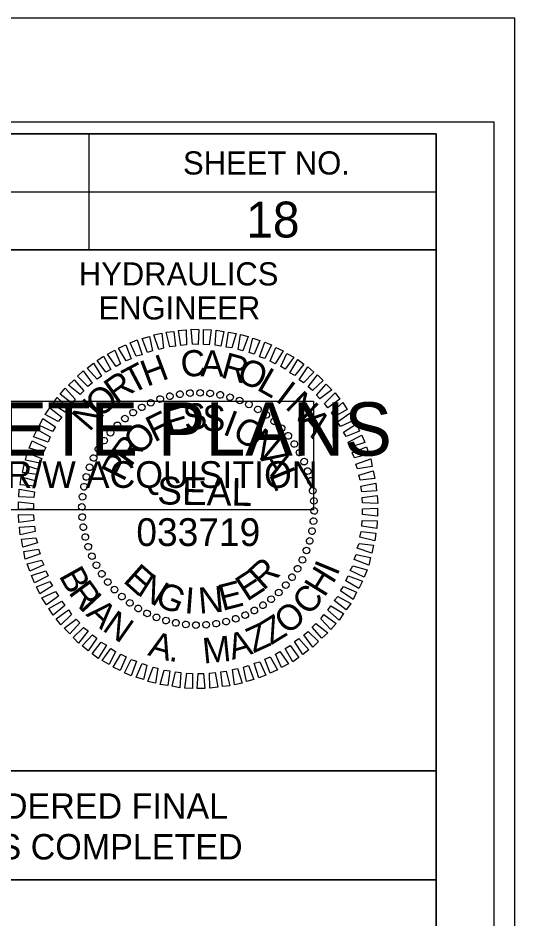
# Model space of a CAD drawing. Extents: x 1779926 to 1781610, y 605564 to 621564.
# Drawn here: x 1781502.6 to 1781610, y 606469.7 to 606664.2 of the extents above; entities that cross this region are included whole.
import ezdxf

# ---------------------------------------------------------------- set-up
doc = ezdxf.new("R2010")
doc.units = 0
for name, color, linetype in [('Old_Level_58', 7, 'Continuous'), ('Sheet Data Field CELL', 7, 'Continuous'), ('Sheet Plot Border Inside CELL', 7, 'Continuous'), ('Sheet Plot Border Outside CELL', 7, 'Continuous'), ('Sheet Professional Seal CELL', 7, 'Continuous'), ('Sheet Profile CELL', 7, 'Continuous'), ('Sheet Profile Grid Major CELL', 7, 'Continuous'), ('Sheet Profile Grid Minor CELL', 7, 'Continuous'), ('Sheet Sticker Exception Certification CELL', 7, 'Continuous'), ('Sheet Sticker Incomplete CELL', 7, 'Continuous')]:
    doc.layers.add(name, color=color, linetype=linetype)

msp = doc.modelspace()

# ---------------------------------------------------------------- linework, layer by layer
at = {"layer": 'Old_Level_58'}
msp.add_lwpolyline([(1781392.96, 606478.15), (1781592.95, 606478.15), (1781592.95, 606414.2), (1781392.96, 606414.2)], close=True, dxfattribs=at)
at = {"layer": 'Sheet Plot Border Inside CELL'}
msp.add_lwpolyline([(1779938.96, 605586.65), (1781605.46, 605586.65), (1781605.46, 606641.75), (1779938.96, 606641.75)], close=True, dxfattribs=at)
at = {"layer": 'Sheet Plot Border Outside CELL'}
msp.add_lwpolyline([(1779925.96, 605564.2), (1781609.96, 605564.2), (1781609.96, 606664.2), (1779925.96, 606664.2)], close=True, dxfattribs=at)
at = {"layer": 'Sheet Professional Seal CELL'}
for p, q in [((1781539.76, 606583.25), (1781539.76, 606583.25)), ((1781541.96, 606583.3), (1781541.96, 606583.3)), ((1781533.31, 606581.95), (1781533.31, 606581.95)), ((1781535.41, 606582.55), (1781535.41, 606582.55)), ((1781537.61, 606582.95), (1781537.61, 606582.95)), ((1781544.16, 606583.15), (1781544.16, 606583.15)), ((1781546.31, 606582.8), (1781546.31, 606582.8)), ((1781548.41, 606582.35), (1781548.41, 606582.35)), ((1781550.51, 606581.65), (1781550.51, 606581.65)), ((1781529.36, 606580.15), (1781529.36, 606580.15)), ((1781531.31, 606581.15), (1781531.31, 606581.15)), ((1781552.51, 606580.75), (1781552.51, 606580.75)), ((1781554.46, 606579.75), (1781554.46, 606579.75)), ((1781525.71, 606577.75), (1781525.71, 606577.75)), ((1781527.46, 606579), (1781527.46, 606579)), ((1781556.26, 606578.5), (1781556.26, 606578.5)), ((1781524.06, 606576.25), (1781524.06, 606576.25)), ((1781558.01, 606577.15), (1781558.01, 606577.15)), ((1781559.56, 606575.65), (1781559.56, 606575.65)), ((1781522.56, 606574.7), (1781522.56, 606574.7)), ((1781561.06, 606574), (1781561.06, 606574)), ((1781521.21, 606572.95), (1781521.21, 606572.95)), ((1781562.31, 606572.25), (1781562.31, 606572.25)), ((1781519.96, 606571.15), (1781519.96, 606571.15)), ((1781563.46, 606570.35), (1781563.46, 606570.35)), ((1781518.96, 606569.2), (1781518.96, 606569.2)), ((1781564.46, 606568.4), (1781564.46, 606568.4)), ((1781518.06, 606567.2), (1781518.06, 606567.2)), ((1781565.26, 606566.4), (1781565.26, 606566.4)), ((1781517.36, 606565.1), (1781517.36, 606565.1)), ((1781565.86, 606564.3), (1781565.86, 606564.3)), ((1781516.91, 606563), (1781516.91, 606563)), ((1781566.26, 606562.1), (1781566.26, 606562.1)), ((1781516.56, 606560.85), (1781516.56, 606560.85)), ((1781566.56, 606559.95), (1781566.56, 606559.95)), ((1781516.41, 606558.65), (1781516.41, 606558.65)), ((1781541.51, 606558.2), (1781541.51, 606558.2)), ((1781516.46, 606556.45), (1781516.46, 606556.45)), ((1781566.61, 606557.75), (1781566.61, 606557.75)), ((1781516.76, 606554.3), (1781516.76, 606554.3)), ((1781566.46, 606555.55), (1781566.46, 606555.55)), ((1781517.16, 606552.1), (1781517.16, 606552.1)), ((1781566.11, 606553.4), (1781566.11, 606553.4)), ((1781565.66, 606551.3), (1781565.66, 606551.3)), ((1781517.76, 606550), (1781517.76, 606550)), ((1781564.96, 606549.2), (1781564.96, 606549.2)), ((1781518.56, 606548), (1781518.56, 606548)), ((1781564.06, 606547.2), (1781564.06, 606547.2)), ((1781519.56, 606546.05), (1781519.56, 606546.05)), ((1781563.06, 606545.25), (1781563.06, 606545.25)), ((1781520.71, 606544.15), (1781520.71, 606544.15)), ((1781521.96, 606542.4), (1781521.96, 606542.4)), ((1781561.81, 606543.45), (1781561.81, 606543.45)), ((1781523.46, 606540.75), (1781523.46, 606540.75)), ((1781560.46, 606541.7), (1781560.46, 606541.7)), ((1781525.01, 606539.25), (1781525.01, 606539.25)), ((1781557.31, 606538.65), (1781557.31, 606538.65)), ((1781558.96, 606540.15), (1781558.96, 606540.15)), ((1781526.76, 606537.9), (1781526.76, 606537.9)), ((1781528.56, 606536.65), (1781528.56, 606536.65)), ((1781555.56, 606537.4), (1781555.56, 606537.4)), ((1781530.51, 606535.65), (1781530.51, 606535.65)), ((1781532.51, 606534.75), (1781532.51, 606534.75)), ((1781551.71, 606535.25), (1781551.71, 606535.25)), ((1781553.66, 606536.25), (1781553.66, 606536.25)), ((1781534.61, 606534.05), (1781534.61, 606534.05)), ((1781536.71, 606533.6), (1781536.71, 606533.6)), ((1781538.86, 606533.25), (1781538.86, 606533.25)), ((1781541.06, 606533.1), (1781541.06, 606533.1)), ((1781543.26, 606533.15), (1781543.26, 606533.15)), ((1781545.41, 606533.45), (1781545.41, 606533.45)), ((1781547.61, 606533.85), (1781547.61, 606533.85)), ((1781549.71, 606534.45), (1781549.71, 606534.45))]:
    msp.add_line(p, q, dxfattribs=at)
for points in [[(1781537.81, 606593.5), (1781537.26, 606596.7), (1781538.96, 606596.9), (1781539.01, 606593.65)], [(1781540.31, 606593.75), (1781540.06, 606597), (1781541.71, 606596.95), (1781541.51, 606593.7)], [(1781542.71, 606593.7), (1781542.71, 606596.95), (1781544.36, 606596.9), (1781543.91, 606593.65)], [(1781530.61, 606592), (1781529.46, 606595), (1781531.01, 606595.45), (1781531.66, 606592.35)], [(1781533.01, 606592.65), (1781531.96, 606595.8), (1781533.66, 606596.15), (1781534.06, 606592.9)], [(1781535.41, 606593.2), (1781534.61, 606596.4), (1781536.26, 606596.55), (1781536.61, 606593.35)], [(1781545.21, 606593.55), (1781545.41, 606596.8), (1781547.06, 606596.5), (1781546.41, 606593.35)], [(1781547.61, 606593.15), (1781548.06, 606596.35), (1781549.71, 606596.1), (1781548.81, 606593)], [(1781550.16, 606592.6), (1781550.66, 606595.85), (1781552.36, 606595.45), (1781551.21, 606592.35)], [(1781552.56, 606591.95), (1781553.31, 606595.05), (1781554.86, 606594.55), (1781553.61, 606591.6)], [(1781525.96, 606590.15), (1781524.36, 606592.95), (1781525.91, 606593.65), (1781527.06, 606590.6)], [(1781528.16, 606591.2), (1781526.86, 606594.1), (1781528.36, 606594.7), (1781529.41, 606591.5)], [(1781554.81, 606591.05), (1781555.96, 606594.2), (1781557.36, 606593.6), (1781555.96, 606590.7)], [(1781557.06, 606590.1), (1781558.31, 606593.05), (1781559.86, 606592.35), (1781558.16, 606589.55)], [(1781521.61, 606587.7), (1781519.76, 606590.25), (1781521.06, 606591.2), (1781522.71, 606588.3)], [(1781523.81, 606588.95), (1781521.96, 606591.65), (1781523.51, 606592.45), (1781524.76, 606589.55)], [(1781559.36, 606588.95), (1781560.71, 606591.8), (1781562.21, 606590.95), (1781560.31, 606588.35)], [(1781519.71, 606586.2), (1781517.56, 606588.6), (1781518.91, 606589.65), (1781520.66, 606586.85)], [(1781561.31, 606587.6), (1781563.06, 606590.5), (1781564.36, 606589.45), (1781562.41, 606587)], [(1781517.71, 606584.65), (1781515.51, 606586.85), (1781516.71, 606588.05), (1781518.66, 606585.35)], [(1781563.36, 606586.1), (1781565.21, 606588.85), (1781566.51, 606587.75), (1781564.31, 606585.4)], [(1781565.26, 606584.55), (1781567.31, 606587.15), (1781568.51, 606585.95), (1781566.21, 606583.8)], [(1781516.06, 606582.9), (1781513.51, 606584.95), (1781514.76, 606586.1), (1781516.86, 606583.7)], [(1781514.31, 606581), (1781511.71, 606582.95), (1781512.81, 606584.25), (1781515.01, 606581.9)], [(1781567.06, 606582.8), (1781569.21, 606585.15), (1781570.41, 606583.95), (1781567.81, 606582)], [(1781568.81, 606581), (1781571.11, 606583.25), (1781572.16, 606581.9), (1781569.51, 606580)], [(1781512.81, 606579.1), (1781510.11, 606580.8), (1781511.06, 606582.25), (1781513.46, 606580.05)], [(1781511.31, 606577.1), (1781508.51, 606578.6), (1781509.51, 606580), (1781512.11, 606578)], [(1781570.31, 606579.05), (1781572.76, 606581.15), (1781573.71, 606579.7), (1781570.91, 606578.1)], [(1781510.11, 606574.95), (1781507.26, 606576.2), (1781508.01, 606577.75), (1781510.71, 606575.9)], [(1781571.61, 606577), (1781574.26, 606578.9), (1781575.21, 606577.4), (1781572.31, 606576)], [(1781572.91, 606574.8), (1781575.71, 606576.55), (1781576.36, 606575), (1781573.51, 606573.85)], [(1781509.11, 606572.65), (1781506.01, 606573.8), (1781506.76, 606575.35), (1781509.61, 606573.75)], [(1781573.91, 606572.65), (1781576.86, 606574.15), (1781577.51, 606572.55), (1781574.41, 606571.55)], [(1781508.11, 606570.45), (1781505.01, 606571.35), (1781505.66, 606572.9), (1781508.66, 606571.5)], [(1781574.81, 606570.3), (1781577.86, 606571.6), (1781578.41, 606570.05), (1781575.31, 606569.25)], [(1781507.36, 606568.05), (1781504.26, 606568.7), (1781504.61, 606570.35), (1781507.76, 606569.1)], [(1781506.71, 606565.65), (1781503.61, 606566.05), (1781503.96, 606567.75), (1781507.11, 606566.7)], [(1781575.61, 606567.9), (1781578.81, 606569.05), (1781579.11, 606567.4), (1781575.96, 606566.85)], [(1781576.21, 606565.5), (1781579.36, 606566.45), (1781579.66, 606564.75), (1781576.51, 606564.45)], [(1781506.31, 606563.1), (1781503.11, 606563.4), (1781503.31, 606565.1), (1781506.56, 606564.3)], [(1781576.66, 606563.1), (1781579.91, 606563.8), (1781580.06, 606562.1), (1781576.86, 606561.9)], [(1781506.06, 606560.7), (1781502.81, 606560.8), (1781502.91, 606562.45), (1781506.16, 606561.9)], [(1781576.96, 606560.7), (1781580.21, 606561.1), (1781580.31, 606559.4), (1781577.06, 606559.5)], [(1781506.01, 606558.2), (1781502.76, 606558.05), (1781502.76, 606559.75), (1781506.01, 606559.4)], [(1781577.01, 606558.2), (1781580.26, 606558.35), (1781580.26, 606556.65), (1781577.01, 606557)], [(1781506.06, 606555.7), (1781502.81, 606555.3), (1781502.71, 606557), (1781505.96, 606556.9)], [(1781506.36, 606553.3), (1781503.11, 606552.6), (1781502.96, 606554.3), (1781506.16, 606554.5)], [(1781576.96, 606555.7), (1781580.21, 606555.6), (1781580.11, 606553.95), (1781576.86, 606554.5)], [(1781576.71, 606553.3), (1781579.91, 606553), (1781579.71, 606551.3), (1781576.46, 606552.1)], [(1781506.81, 606550.9), (1781503.66, 606549.95), (1781503.36, 606551.65), (1781506.51, 606551.95)], [(1781576.31, 606550.75), (1781579.41, 606550.35), (1781579.06, 606548.65), (1781575.91, 606549.7)], [(1781507.41, 606548.5), (1781504.21, 606547.35), (1781503.91, 606549), (1781507.06, 606549.55)], [(1781575.66, 606548.35), (1781578.76, 606547.7), (1781578.41, 606546.05), (1781575.26, 606547.3)], [(1781508.21, 606546.1), (1781505.16, 606544.8), (1781504.61, 606546.35), (1781507.71, 606547.15)], [(1781509.11, 606543.75), (1781506.16, 606542.25), (1781505.51, 606543.85), (1781508.61, 606544.85)], [(1781574.91, 606545.95), (1781578.01, 606545.05), (1781577.36, 606543.5), (1781574.36, 606544.9)], [(1781510.11, 606541.6), (1781507.31, 606539.85), (1781506.66, 606541.4), (1781509.51, 606542.55)], [(1781573.91, 606543.75), (1781577.01, 606542.6), (1781576.26, 606541.05), (1781573.41, 606542.65)], [(1781572.91, 606541.45), (1781575.76, 606540.2), (1781575.01, 606538.65), (1781572.31, 606540.5)], [(1781511.41, 606539.4), (1781508.76, 606537.5), (1781507.81, 606539), (1781510.71, 606540.4)], [(1781571.71, 606539.3), (1781574.51, 606537.8), (1781573.51, 606536.4), (1781570.91, 606538.4)], [(1781512.71, 606537.35), (1781510.26, 606535.25), (1781509.31, 606536.7), (1781512.11, 606538.3)], [(1781570.21, 606537.3), (1781572.91, 606535.6), (1781571.96, 606534.15), (1781569.56, 606536.35)], [(1781514.21, 606535.4), (1781511.91, 606533.15), (1781510.86, 606534.5), (1781513.51, 606536.4)], [(1781568.71, 606535.4), (1781571.31, 606533.45), (1781570.21, 606532.15), (1781568.01, 606534.5)], [(1781515.96, 606533.6), (1781513.81, 606531.25), (1781512.61, 606532.45), (1781515.21, 606534.4)], [(1781566.96, 606533.5), (1781569.51, 606531.45), (1781568.26, 606530.3), (1781566.16, 606532.7)], [(1781517.76, 606531.85), (1781515.71, 606529.25), (1781514.51, 606530.45), (1781516.81, 606532.6)], [(1781519.66, 606530.3), (1781517.81, 606527.55), (1781516.51, 606528.65), (1781518.71, 606531)], [(1781565.31, 606531.75), (1781567.51, 606529.55), (1781566.31, 606528.35), (1781564.36, 606531.05)], [(1781521.71, 606528.8), (1781519.96, 606525.9), (1781518.66, 606526.95), (1781520.61, 606529.4)], [(1781563.31, 606530.2), (1781565.46, 606527.8), (1781564.11, 606526.75), (1781562.36, 606529.55)], [(1781523.66, 606527.45), (1781522.31, 606524.6), (1781520.81, 606525.45), (1781522.71, 606528.05)], [(1781525.96, 606526.3), (1781524.71, 606523.35), (1781523.16, 606524.05), (1781524.86, 606526.85)], [(1781559.21, 606527.45), (1781561.06, 606524.75), (1781559.51, 606523.95), (1781558.26, 606526.85)], [(1781561.41, 606528.7), (1781563.26, 606526.15), (1781561.96, 606525.2), (1781560.31, 606528.1)], [(1781528.21, 606525.35), (1781527.06, 606522.2), (1781525.66, 606522.8), (1781527.06, 606525.7)], [(1781554.86, 606525.2), (1781556.16, 606522.3), (1781554.66, 606521.7), (1781553.61, 606524.9)], [(1781557.06, 606526.25), (1781558.66, 606523.45), (1781557.11, 606522.75), (1781555.96, 606525.8)], [(1781530.46, 606524.45), (1781529.71, 606521.35), (1781528.16, 606521.85), (1781529.41, 606524.8)], [(1781532.86, 606523.8), (1781532.36, 606520.55), (1781530.66, 606520.95), (1781531.81, 606524.05)], [(1781535.41, 606523.25), (1781534.96, 606520.05), (1781533.31, 606520.3), (1781534.21, 606523.4)], [(1781537.81, 606522.85), (1781537.61, 606519.6), (1781535.96, 606519.9), (1781536.61, 606523.05)], [(1781547.61, 606523.2), (1781548.41, 606520), (1781546.76, 606519.85), (1781546.41, 606523.05)], [(1781550.01, 606523.75), (1781551.06, 606520.6), (1781549.36, 606520.25), (1781548.96, 606523.5)], [(1781552.41, 606524.4), (1781553.56, 606521.4), (1781552.01, 606520.95), (1781551.36, 606524.05)], [(1781540.31, 606522.7), (1781540.31, 606519.45), (1781538.66, 606519.5), (1781539.11, 606522.75)], [(1781542.71, 606522.65), (1781542.96, 606519.4), (1781541.31, 606519.45), (1781541.51, 606522.7)], [(1781545.21, 606522.9), (1781545.76, 606519.7), (1781544.06, 606519.5), (1781544.01, 606522.75)]]:
    msp.add_lwpolyline(points, close=True, dxfattribs=at)
for centre, major_axis in [((1781535.44, 606582.54), (-0.174, 0.699)), ((1781537.59, 606582.98), (-0.113, 0.711)), ((1781539.76, 606583.22), (-0.05, 0.718)), ((1781541.95, 606583.28), (0.013, 0.72)), ((1781544.13, 606583.15), (0.075, 0.716)), ((1781546.3, 606582.82), (0.137, 0.707)), ((1781531.31, 606581.12), (-0.293, 0.658)), ((1781533.34, 606581.92), (-0.234, 0.681)), ((1781548.42, 606582.31), (0.198, 0.692)), ((1781550.5, 606581.62), (0.258, 0.672)), ((1781552.5, 606580.75), (0.316, 0.647)), ((1781527.49, 606579), (-0.403, 0.597)), ((1781529.35, 606580.14), (-0.349, 0.63)), ((1781554.43, 606579.7), (0.371, 0.617)), ((1781525.73, 606577.7), (-0.453, 0.56)), ((1781556.25, 606578.49), (0.423, 0.582)), ((1781557.96, 606577.13), (0.472, 0.543)), ((1781522.58, 606574.66), (-0.543, 0.472)), ((1781524.09, 606576.25), (-0.5, 0.518)), ((1781559.55, 606575.63), (0.518, 0.5)), ((1781521.22, 606572.95), (-0.582, 0.423)), ((1781561, 606573.99), (0.56, 0.453)), ((1781520.01, 606571.12), (-0.617, 0.371)), ((1781562.3, 606572.23), (0.597, 0.403)), ((1781518.97, 606569.2), (-0.647, 0.316)), ((1781563.45, 606570.36), (0.63, 0.349)), ((1781518.1, 606567.19), (-0.672, 0.258)), ((1781564.42, 606568.41), (0.658, 0.293)), ((1781517.4, 606565.12), (-0.692, 0.198)), ((1781565.22, 606566.37), (0.681, 0.234)), ((1781516.89, 606562.99), (-0.707, 0.137)), ((1781565.84, 606564.27), (0.699, 0.174)), ((1781566.28, 606562.13), (0.711, 0.113)), ((1781516.57, 606560.83), (-0.716, 0.075)), ((1781566.53, 606559.95), (0.718, 0.05)), ((1781516.43, 606558.64), (-0.72, 0.013)), ((1781566.59, 606557.77), (0.72, -0.013)), ((1781516.49, 606556.45), (-0.718, -0.05)), ((1781566.45, 606555.58), (0.716, -0.075)), ((1781516.74, 606554.28), (-0.711, -0.113)), ((1781566.13, 606553.42), (0.707, -0.137)), ((1781517.17, 606552.14), (-0.699, -0.174)), ((1781517.8, 606550.04), (-0.681, -0.234)), ((1781565.62, 606551.29), (0.692, -0.198)), ((1781518.6, 606548), (-0.658, -0.293)), ((1781564.92, 606549.22), (0.672, -0.258)), ((1781519.57, 606546.05), (-0.63, -0.349)), ((1781564.05, 606547.21), (0.647, -0.316)), ((1781520.72, 606544.18), (-0.597, -0.403)), ((1781563.01, 606545.29), (0.617, -0.371)), ((1781522.02, 606542.42), (-0.56, -0.453)), ((1781560.44, 606541.75), (0.543, -0.472)), ((1781561.8, 606543.46), (0.582, -0.423)), ((1781523.47, 606540.78), (-0.518, -0.5)), ((1781558.93, 606540.16), (0.5, -0.518)), ((1781525.06, 606539.28), (-0.472, -0.543)), ((1781526.77, 606537.91), (-0.423, -0.582)), ((1781557.29, 606538.71), (0.453, -0.56)), ((1781528.59, 606536.71), (-0.371, -0.617)), ((1781553.67, 606536.27), (0.349, -0.63)), ((1781555.53, 606537.41), (0.403, -0.597)), ((1781530.52, 606535.66), (-0.316, -0.647)), ((1781532.52, 606534.79), (-0.258, -0.672)), ((1781534.6, 606534.1), (-0.198, -0.692)), ((1781547.58, 606533.87), (0.174, -0.699)), ((1781549.67, 606534.49), (0.234, -0.681)), ((1781551.71, 606535.29), (0.293, -0.658)), ((1781536.72, 606533.59), (-0.137, -0.707)), ((1781538.89, 606533.26), (-0.075, -0.716)), ((1781541.07, 606533.13), (-0.013, -0.72)), ((1781543.26, 606533.19), (0.05, -0.718)), ((1781545.43, 606533.43), (0.113, -0.711))]:
    msp.add_ellipse(centre, major_axis=major_axis, ratio=0.999708, dxfattribs=at)
at = {"layer": 'Sheet Profile CELL'}
for p, q in [((1781517.96, 606639.15), (1781517.96, 606614.15)), ((1781392.91, 606626.65), (1781592.96, 606626.65))]:
    msp.add_line(p, q, dxfattribs=at)
for points in [[(1781592.96, 606639.2), (1780092.96, 606639.2), (1780092.96, 605589.2), (1781592.96, 605589.2)], [(1781392.91, 606639.2), (1781592.96, 606639.2), (1781592.96, 606614.15), (1781392.91, 606614.15)], [(1781492.96, 606614.15), (1781592.96, 606614.15), (1781592.96, 606501.65), (1781492.96, 606501.65)]]:
    msp.add_lwpolyline(points, close=True, dxfattribs=at)
at = {"layer": 'Sheet Profile Grid Major CELL'}
msp.add_lwpolyline([(1781542.96, 606414.2), (1781542.96, 606139.2), (1781592.96, 606139.2), (1781592.96, 606489.2)], dxfattribs=at)
at = {"layer": 'Sheet Sticker Exception Certification CELL'}
for p, q in [((1781392.91, 606501.65), (1781592.95, 606501.65)), ((1781392.91, 606501.65), (1781592.95, 606501.65)), ((1781592.95, 606501.64), (1781592.95, 606478.14)), ((1781592.95, 606501.64), (1781592.95, 606478.14)), ((1781592.95, 606478.15), (1781392.91, 606478.15)), ((1781592.95, 606478.15), (1781392.91, 606478.15))]:
    msp.add_line(p, q, dxfattribs=at)
at = {"layer": 'Sheet Sticker Incomplete CELL'}
msp.add_lwpolyline([(1781419.48, 606558), (1781419.48, 606581.5), (1781566.48, 606581.5), (1781566.48, 606558)], close=True, dxfattribs=at)

# ---------------------------------------------------------------- texts
at = {"layer": 'Sheet Data Field CELL'}
msp.add_text('18', height=7.75, dxfattribs=at).set_placement((1781551.91, 606616.81))
at = {"layer": 'Sheet Professional Seal CELL'}
for s, height, rotation, p in [('H', 5.64, 20.6195, (1781530.46, 606584.55)), ('C', 5.64, 6.2199, (1781538.06, 606586.55)), ('A', 5.64, 359.0203, (1781542.01, 606586.85)), ('R', 5.64, 344.6211, (1781546.21, 606586.65)), ('T', 5.64, 27.8198, (1781527.21, 606582.9)), ('O', 5.64, 337.4212, (1781549.56, 606585.9)), ('R', 5.64, 35.0205, (1781523.81, 606580.7)), ('L', 5.64, 330.2209, (1781553.96, 606584.05)), ('I', 5.64, 323.0201, (1781558.01, 606581.65)), ('O', 5.64, 42.2217, (1781520.36, 606577.6)), ('N', 5.64, 315.8189, (1781560.16, 606580.1)), ('N', 5.64, 49.4235, (1781518.06, 606574.7)), ('F', 5.64, 25.967, (1781532.06, 606572.5)), ('E', 5.64, 16.6111, (1781535.26, 606574)), ('S', 5.64, 7.2556, (1781538.71, 606575.05)), ('S', 5.64, 357.9004, (1781542.31, 606575.1)), ('I', 5.64, 339.1896, (1781546.61, 606574.4)), ('O', 5.64, 329.8335, (1781548.61, 606573.7)), ('A', 5.64, 308.6172, (1781563.11, 606577.15)), ('O', 5.64, 44.6812, (1781528.76, 606569.55)), ('N', 5.64, 320.4766, (1781551.96, 606571.7)), ('R', 5.64, 54.0397, (1781527.01, 606567.1)), ('P', 5.64, 63.3989, (1781525.41, 606563.9)), ('A', 5.64, 301.7603, (1781554.81, 606569.1)), ('L', 5.64, 292.4008, (1781556.76, 606565.65)), ('SEAL', 5.998, 359, (1781532.66, 606559.2)), ('E', 5.64, 318.2769, (1781525.11, 606542.55)), ('R', 5.64, 42.4814, (1781555.61, 606540.45)), ('E', 5.64, 33.1241, (1781552.06, 606538.1)), ('N', 5.64, 327.634, (1781528.11, 606539.85)), ('E', 5.64, 14.4118, (1781546.76, 606536.15)), ('G', 5.64, 336.9902, (1781531.91, 606537.6)), ('I', 5.64, 355.7012, (1781538.46, 606535.7)), ('N', 5.64, 5.0564, (1781541.81, 606535.55))]:
    msp.add_text(s, height=height, rotation=rotation, dxfattribs=at).set_placement(p)
at = {"layer": 'Sheet Profile CELL'}
for s, p in [('SHEET NO.', (1781538.27, 606630.41)), ('HYDRAULICS', (1781515.77, 606606.46)), ('ENGINEER', (1781520.02, 606599.11))]:
    msp.add_text(s, height=5, dxfattribs=at).set_placement(p)
at = {"layer": 'Sheet Profile Grid Minor CELL'}
msp.add_text('033719', height=5.998, dxfattribs=at).set_placement((1781528.19, 606550.2))
for s, rotation, p in [('I', 67.5926, (1781571.56, 606543.57)), ('B', 299.1529, (1781511.36, 606543.76)), ('H', 58.3478, (1781568.82, 606538.93)), ('R', 306.2797, (1781513.39, 606540.13)), ('C', 49.4751, (1781565.52, 606534.95)), ('I', 313.2061, (1781515.77, 606536.88)), ('A', 316.7266, (1781517.13, 606535.33)), ('O', 38.7706, (1781560.78, 606530.89)), ('N', 324.9124, (1781520.63, 606532.1)), ('Z', 31.6438, (1781557.25, 606528.71)), ('Z', 24.517, (1781553.47, 606526.99)), ('A', 344.2893, (1781530.48, 606526.65)), ('M', 5.6554, (1781542.73, 606524.8)), ('A', 16.3312, (1781548.9, 606525.6)), ('.', 352.4751, (1781535.08, 606525.4))]:
    msp.add_text(s, height=5.5, rotation=rotation, dxfattribs=at).set_placement(p)
at = {"layer": 'Sheet Sticker Exception Certification CELL'}
for s, p in [('DOCUMENT NOT CONSIDERED FINAL', (1781413.98, 606491.31)), ('DOCUMENT NOT CONSIDERED FINAL', (1781413.98, 606491.31)), ('UNLESS ALL SIGNATURES COMPLETED', (1781408.91, 606482.51)), ('UNLESS ALL SIGNATURES COMPLETED', (1781408.91, 606482.51))]:
    msp.add_text(s, height=5.5, dxfattribs=at).set_placement(p)
at = {"layer": 'Sheet Sticker Incomplete CELL'}
for s, height, p in [('INCOMPLETE PLANS', 11.52, (1781428.43, 606569.7)), ('DO NOT USE FOR R/W ACQUISITION', 5.76, (1781431.68, 606562.75))]:
    msp.add_text(s, height=height, dxfattribs=at).set_placement(p)

doc.saveas('drawing.dxf')
